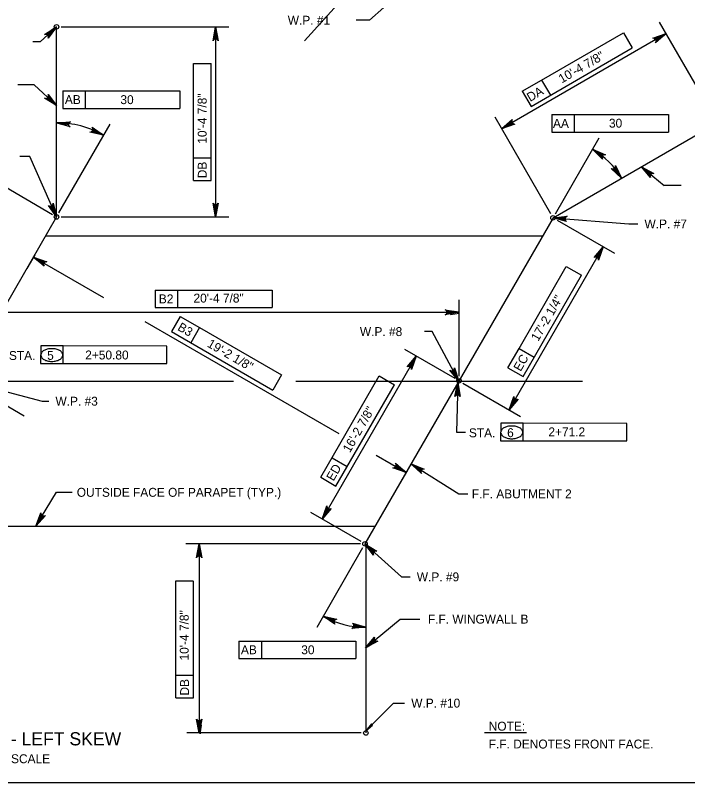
# Model space of a CAD drawing. Extents: x 179 to 454, y -271 to 54.
# Drawn here: x 226.08 to 235.14, y -87.25 to -76.92 of the extents above; entities that cross this region are included whole.
import ezdxf

# ---------------------------------------------------------------- set-up
doc = ezdxf.new("R2010")
doc.units = 0
for name, color, linetype in [('Level 1', 7, 'Continuous'), ('Level 2', 7, 'Continuous'), ('Level 3', 7, 'Continuous'), ('Level 4', 7, 'Continuous'), ('Level 41', 7, 'Continuous'), ('Level 5', 7, 'Continuous')]:
    doc.layers.add(name, color=color, linetype=linetype)

msp = doc.modelspace()

# ---------------------------------------------------------------- linework, layer by layer
at = {"layer": 'Level 1'}
msp.add_lwpolyline([(211.497, -87.25), (242.997, -87.25), (242.997, -66.75), (211.497, -66.75)], close=True, dxfattribs=at)
at = {"layer": 'Level 2'}
for p, q in [((226.635, -79.633), (226.635, -77.074)), ((233.325, -79.645), (235.541, -78.365)), ((226.635, -79.633), (224.1, -84.024)), ((233.325, -79.645), (230.79, -84.035)), ((226.488, -79.888), (233.184, -79.888)), ((225.306, -83.795), (230.928, -83.795)), ((230.803, -84.035), (230.803, -86.581)), ((232.399, -86.575), (232.968, -86.575))]:
    msp.add_line(p, q, dxfattribs=at)
at = {"layer": 'Level 3'}
for p, q in [((223.48, -81.844), (229.019, -81.844)), ((229.857, -81.844), (233.723, -81.844))]:
    msp.add_line(p, q, dxfattribs=at)
for centre in [(226.635, -77.074), (226.635, -79.633), (233.325, -79.645), (232.057, -81.84), (230.79, -84.035), (230.803, -86.581)]:
    msp.add_circle(centre, 0.0304, dxfattribs=at)
at = {"layer": 'Level 4'}
for p, q in [((235.51, -78.312), (234.76, -77.012)), ((226.696, -77.074), (228.955, -77.074)), ((228.778, -77.074), (228.778, -79.633)), ((234.848, -77.165), (232.632, -78.445)), ((233.171, -77.79), (234.273, -77.153)), ((234.273, -77.153), (234.391, -77.358)), ((233.028, -78.145), (234.391, -77.358)), ((228.48, -77.566), (228.716, -77.566)), ((228.48, -78.839), (228.48, -77.566)), ((228.716, -79.141), (228.716, -77.566)), ((232.909, -77.941), (233.171, -77.79)), ((233.171, -77.79), (233.289, -77.994)), ((226.719, -77.935), (227.022, -77.935)), ((226.719, -77.935), (226.719, -78.171)), ((227.022, -77.935), (227.022, -78.171)), ((227.022, -77.935), (228.294, -77.935)), ((228.294, -77.935), (228.294, -78.171)), ((232.909, -77.941), (233.028, -78.145)), ((226.719, -78.171), (228.294, -78.171)), ((233.294, -79.591), (232.543, -78.291)), ((233.307, -78.256), (233.609, -78.256)), ((233.307, -78.256), (233.307, -78.492)), ((233.609, -78.256), (233.609, -78.492)), ((233.609, -78.256), (234.882, -78.256)), ((234.882, -78.256), (234.882, -78.492)), ((226.666, -79.58), (227.357, -78.382)), ((233.307, -78.492), (234.882, -78.492)), ((233.356, -79.591), (233.946, -78.569)), ((228.48, -79.141), (228.48, -78.839)), ((228.48, -78.839), (228.716, -78.839)), ((226.582, -79.603), (225.859, -79.185)), ((228.48, -79.141), (228.716, -79.141)), ((234.818, -79.207), (235.049, -79.207)), ((226.696, -79.633), (228.955, -79.633)), ((233.378, -79.675), (234.154, -80.123)), ((232.733, -82.23), (234, -80.035)), ((226.34, -80.145), (226.234, -80.327)), ((226.323, -80.174), (227.266, -80.718)), ((232.866, -81.403), (233.502, -80.301)), ((233.502, -80.301), (233.707, -80.419)), ((232.92, -81.783), (233.707, -80.419)), ((227.964, -80.618), (228.266, -80.618)), ((227.964, -80.618), (227.964, -80.854)), ((228.266, -80.618), (228.266, -80.854)), ((228.266, -80.618), (229.539, -80.618)), ((229.539, -80.618), (229.539, -80.854)), ((232.058, -81.778), (232.059, -80.75)), ((227.964, -80.854), (229.539, -80.854)), ((225.369, -80.916), (232.059, -80.916)), ((228.301, -80.972), (228.183, -81.177)), ((228.301, -80.972), (228.563, -81.123)), ((227.825, -81.041), (230.44, -82.551)), ((228.183, -81.177), (229.547, -81.964)), ((228.563, -81.123), (228.445, -81.328)), ((228.563, -81.123), (229.665, -81.76)), ((226.421, -81.37), (226.42, -81.606)), ((226.723, -81.37), (226.421, -81.37)), ((228.121, -81.372), (226.723, -81.37)), ((226.723, -81.607), (226.723, -81.37)), ((228.121, -81.608), (228.121, -81.372)), ((232.715, -81.665), (232.866, -81.403)), ((232.866, -81.403), (233.071, -81.521)), ((231.481, -81.507), (230.213, -83.702)), ((232.004, -81.809), (231.327, -81.418)), ((226.42, -81.606), (228.121, -81.608)), ((232.715, -81.665), (232.92, -81.783)), ((229.665, -81.76), (229.547, -81.964)), ((230.195, -83.138), (230.983, -81.774)), ((230.983, -81.774), (231.188, -81.892)), ((225.421, -81.859), (226.2, -82.309)), ((230.4, -83.256), (231.188, -81.892)), ((232.043, -81.864), (232.023, -82.533)), ((232.111, -81.871), (232.886, -82.318)), ((232.619, -82.411), (232.618, -82.647)), ((232.921, -82.412), (232.619, -82.411)), ((234.319, -82.413), (232.921, -82.412)), ((232.921, -82.648), (232.921, -82.412)), ((234.319, -82.649), (234.319, -82.413)), ((232.023, -82.533), (232.143, -82.533)), ((232.618, -82.647), (234.319, -82.649)), ((230.941, -82.84), (231.345, -83.073)), ((230.347, -82.876), (230.551, -82.994)), ((231.412, -82.958), (232.057, -83.362)), ((231.362, -83.044), (231.256, -83.227)), ((230.195, -83.138), (230.4, -83.256)), ((226.633, -83.341), (226.847, -83.341)), ((232.057, -83.362), (232.177, -83.362)), ((230.737, -84.004), (230.06, -83.614)), ((230.728, -84.035), (228.378, -84.035)), ((228.556, -84.035), (228.556, -86.581)), ((230.759, -84.088), (230.14, -85.161)), ((228.24, -84.533), (228.47, -84.532)), ((228.24, -85.805), (228.24, -84.533)), ((228.478, -86.106), (228.478, -84.532)), ((231.265, -85.049), (231.528, -85.049)), ((229.092, -85.343), (229.394, -85.343)), ((229.092, -85.343), (229.092, -85.579)), ((229.394, -85.343), (229.394, -85.579)), ((229.394, -85.343), (230.666, -85.343)), ((230.666, -85.343), (230.666, -85.579)), ((229.092, -85.579), (230.666, -85.579)), ((228.24, -85.805), (228.476, -85.804)), ((228.242, -86.108), (228.24, -85.805)), ((228.242, -86.108), (228.478, -86.106)), ((230.741, -86.581), (228.391, -86.581))]:
    msp.add_line(p, q, dxfattribs=at)
for points in [[(231.236, -76.64), (230.851, -76.985), (230.672, -76.985)], [(226.635, -77.074), (226.415, -77.276), (226.313, -77.276)], [(234.848, -77.165), (234.704, -77.289), (234.712, -77.273), (234.712, -77.258), (234.707, -77.247), (234.699, -77.237), (234.687, -77.23), (234.669, -77.228), (234.848, -77.165), (234.687, -77.23), (234.699, -77.237), (234.848, -77.165), (234.707, -77.247), (234.712, -77.258), (234.848, -77.165), (234.712, -77.273)], [(226.635, -78.135), (226.333, -77.856)], [(232.632, -78.445), (232.776, -78.321), (232.769, -78.337), (232.768, -78.352), (232.773, -78.364), (232.781, -78.373), (232.794, -78.38), (232.811, -78.382), (232.632, -78.445), (232.794, -78.38), (232.781, -78.373), (232.632, -78.445), (232.773, -78.364), (232.768, -78.352), (232.632, -78.445), (232.769, -78.337)], [(233.857, -78.722), (234.032, -78.796), (234.014, -78.796), (234.001, -78.802), (233.993, -78.812), (233.988, -78.823), (233.987, -78.838), (233.993, -78.854), (233.857, -78.722), (233.987, -78.838), (233.988, -78.823), (233.857, -78.722), (233.993, -78.812), (234.001, -78.802), (233.857, -78.722), (234.014, -78.796)], [(226.635, -79.633), (226.275, -78.82), (226.142, -78.82)], [(234.247, -79.112), (234.11, -78.981), (234.126, -78.987), (234.141, -78.986), (234.152, -78.98), (234.161, -78.971), (234.167, -78.958), (234.166, -78.941), (234.247, -79.112), (234.167, -78.958), (234.161, -78.971), (234.247, -79.112), (234.152, -78.98), (234.141, -78.986), (234.247, -79.112), (234.126, -78.987)], [(234.515, -78.957), (234.822, -79.21)], [(234.515, -78.957), (234.681, -79.049), (234.664, -79.048), (234.65, -79.052), (234.641, -79.061), (234.634, -79.072), (234.632, -79.086), (234.637, -79.103), (234.515, -78.957), (234.632, -79.086), (234.634, -79.072), (234.515, -78.957), (234.641, -79.061), (234.65, -79.052), (234.515, -78.957), (234.664, -79.048)], [(233.325, -79.645), (233.513, -79.625), (233.498, -79.634), (233.49, -79.645), (233.487, -79.658), (233.488, -79.67), (233.494, -79.683), (233.508, -79.695), (233.325, -79.645), (233.494, -79.683), (233.488, -79.67), (233.325, -79.645), (233.487, -79.658), (233.49, -79.645), (233.325, -79.645), (233.498, -79.634)], [(233.325, -79.645), (234.345, -79.728), (234.468, -79.728)], [(234, -80.035), (233.937, -80.213), (233.936, -80.196), (233.929, -80.183), (233.919, -80.175), (233.907, -80.171), (233.892, -80.171), (233.877, -80.179), (234, -80.035), (233.892, -80.171), (233.907, -80.171), (234, -80.035), (233.919, -80.175), (233.929, -80.183), (234, -80.035), (233.936, -80.196)], [(232.059, -80.916), (231.873, -80.951), (231.887, -80.941), (231.894, -80.929), (231.896, -80.916), (231.894, -80.904), (231.887, -80.891), (231.873, -80.882), (232.059, -80.916), (231.887, -80.891), (231.894, -80.904), (232.059, -80.916), (231.896, -80.916), (231.894, -80.929), (232.059, -80.916), (231.887, -80.941)], [(232.055, -81.844), (231.696, -81.177), (231.592, -81.177)], [(231.481, -81.507), (231.418, -81.686), (231.416, -81.668), (231.409, -81.656), (231.399, -81.648), (231.388, -81.643), (231.373, -81.643), (231.357, -81.651), (231.481, -81.507), (231.373, -81.643), (231.388, -81.643), (231.481, -81.507), (231.399, -81.648), (231.409, -81.656), (231.481, -81.507), (231.416, -81.668)], [(232.055, -81.844), (231.936, -81.696), (231.951, -81.704), (231.966, -81.705), (231.978, -81.701), (231.988, -81.693), (231.995, -81.68), (231.997, -81.663), (232.055, -81.844), (231.995, -81.68), (231.988, -81.693), (232.055, -81.844), (231.978, -81.701), (231.966, -81.705), (232.055, -81.844), (231.951, -81.704)], [(225.368, -81.829), (226.44, -82.114), (226.531, -82.114)], [(232.043, -81.864), (232.072, -82.052), (232.063, -82.037), (232.051, -82.029), (232.038, -82.027), (232.026, -82.029), (232.013, -82.036), (232.003, -82.05), (232.043, -81.864), (232.013, -82.036), (232.026, -82.029), (232.043, -81.864), (232.038, -82.027), (232.051, -82.029), (232.043, -81.864), (232.063, -82.037)], [(232.733, -82.23), (232.796, -82.051), (232.797, -82.068), (232.804, -82.081), (232.814, -82.089), (232.826, -82.093), (232.84, -82.093), (232.856, -82.086), (232.733, -82.23), (232.84, -82.093), (232.826, -82.093), (232.733, -82.23), (232.814, -82.089), (232.804, -82.081), (232.733, -82.23), (232.797, -82.068)], [(231.345, -83.073), (231.166, -83.011), (231.184, -83.009), (231.196, -83.002), (231.204, -82.992), (231.209, -82.98), (231.209, -82.966), (231.201, -82.95), (231.345, -83.073), (231.209, -82.966), (231.209, -82.98), (231.345, -83.073), (231.204, -82.992), (231.196, -83.002), (231.345, -83.073), (231.184, -83.009)], [(231.412, -82.958), (231.589, -83.027), (231.571, -83.028), (231.558, -83.034), (231.55, -83.044), (231.545, -83.056), (231.545, -83.07), (231.552, -83.086), (231.412, -82.958), (231.545, -83.07), (231.545, -83.056), (231.412, -82.958), (231.55, -83.044), (231.558, -83.034), (231.412, -82.958), (231.571, -83.028)], [(226.357, -83.795), (226.633, -83.341)], [(230.213, -83.702), (230.276, -83.523), (230.278, -83.541), (230.285, -83.553), (230.295, -83.561), (230.306, -83.566), (230.321, -83.566), (230.337, -83.558), (230.213, -83.702), (230.321, -83.566), (230.306, -83.566), (230.213, -83.702), (230.295, -83.561), (230.285, -83.553), (230.213, -83.702), (230.278, -83.541)], [(226.357, -83.795), (226.424, -83.618), (226.425, -83.635), (226.432, -83.648), (226.441, -83.656), (226.453, -83.661), (226.468, -83.661), (226.484, -83.654), (226.357, -83.795), (226.468, -83.661), (226.453, -83.661), (226.357, -83.795), (226.441, -83.656), (226.432, -83.648), (226.357, -83.795), (226.425, -83.635)], [(228.556, -84.035), (228.591, -84.222), (228.581, -84.207), (228.568, -84.2), (228.556, -84.198), (228.543, -84.2), (228.531, -84.207), (228.521, -84.222), (228.556, -84.035), (228.531, -84.207), (228.543, -84.2), (228.556, -84.035), (228.556, -84.198), (228.568, -84.2), (228.556, -84.035), (228.581, -84.207)], [(230.79, -84.035), (231.284, -84.479), (231.401, -84.479)], [(230.79, -84.035), (230.952, -84.134), (230.935, -84.131), (230.921, -84.136), (230.911, -84.144), (230.904, -84.154), (230.901, -84.169), (230.905, -84.186), (230.79, -84.035), (230.901, -84.169), (230.904, -84.154), (230.79, -84.035), (230.911, -84.144), (230.921, -84.136), (230.79, -84.035), (230.935, -84.131)], [(230.228, -85.008), (230.413, -85.051), (230.396, -85.054), (230.384, -85.062), (230.377, -85.073), (230.374, -85.085), (230.376, -85.1), (230.385, -85.115), (230.228, -85.008), (230.376, -85.1), (230.374, -85.085), (230.228, -85.008), (230.377, -85.073), (230.384, -85.062), (230.228, -85.008), (230.396, -85.054)], [(230.803, -85.157), (230.613, -85.173), (230.629, -85.164), (230.637, -85.153), (230.641, -85.14), (230.64, -85.128), (230.634, -85.114), (230.621, -85.103), (230.803, -85.157), (230.634, -85.114), (230.64, -85.128), (230.803, -85.157), (230.641, -85.14), (230.637, -85.153), (230.803, -85.157), (230.629, -85.164)], [(230.797, -85.434), (231.265, -85.049)], [(230.797, -85.434), (230.919, -85.289), (230.914, -85.305), (230.916, -85.32), (230.922, -85.331), (230.932, -85.339), (230.946, -85.344), (230.963, -85.343), (230.797, -85.434), (230.946, -85.344), (230.932, -85.339), (230.797, -85.434), (230.922, -85.331), (230.916, -85.32), (230.797, -85.434), (230.914, -85.305)], [(230.803, -86.551), (231.174, -86.179), (231.325, -86.179)], [(228.556, -86.581), (228.521, -86.395), (228.531, -86.409), (228.543, -86.417), (228.556, -86.419), (228.568, -86.417), (228.581, -86.409), (228.591, -86.395), (228.556, -86.581), (228.581, -86.409), (228.568, -86.417), (228.556, -86.581), (228.556, -86.419), (228.543, -86.417), (228.556, -86.581), (228.531, -86.409)]]:
    msp.add_lwpolyline(points, dxfattribs=at)
for points in [[(226.635, -77.074), (226.541, -77.147), (226.555, -77.161)], [(228.758, -77.192), (228.797, -77.192), (228.778, -77.074)], [(234.736, -77.207), (234.756, -77.241), (234.848, -77.165)], [(226.635, -78.135), (226.555, -78.048), (226.542, -78.062)], [(232.725, -78.369), (232.744, -78.403), (232.632, -78.445)], [(226.635, -79.633), (226.596, -79.522), (226.578, -79.529)], [(228.758, -79.515), (228.797, -79.515), (228.778, -79.633)], [(233.325, -79.645), (233.442, -79.664), (233.443, -79.644)], [(233.924, -80.127), (233.958, -80.147), (234, -80.035)], [(226.435, -80.216), (226.415, -80.25), (226.323, -80.174)], [(231.941, -80.908), (231.941, -80.947), (232.059, -80.927)], [(231.405, -81.599), (231.439, -81.619), (231.481, -81.507)], [(232.055, -81.844), (232.008, -81.735), (231.99, -81.745)], [(232.019, -81.985), (232.059, -81.986), (232.044, -81.866)], [(232.775, -82.118), (232.809, -82.137), (232.733, -82.23)], [(231.253, -82.997), (231.233, -83.031), (231.345, -83.073)], [(231.519, -83.048), (231.54, -83.014), (231.428, -82.968)], [(230.255, -83.59), (230.289, -83.61), (230.213, -83.702)], [(226.357, -83.795), (226.427, -83.699), (226.41, -83.689)], [(228.575, -84.164), (228.536, -84.164), (228.555, -84.046)], [(230.79, -84.035), (230.871, -84.121), (230.884, -84.107)], [(230.797, -85.434), (230.894, -85.367), (230.882, -85.352)], [(230.803, -86.551), (230.893, -86.474), (230.879, -86.46)], [(228.587, -86.474), (228.548, -86.474), (228.568, -86.592)]]:
    msp.add_lwpolyline(points, close=True, dxfattribs=at)
for centre, radius, start, end in [((226.635, -79.633), 1.268, 60.0012, 89.9999), ((233.325, -79.645), 1.065, 30, 60.0009), ((226.57, -81.667), 0.26, 90, 103.3749), ((226.57, -81.667), 0.26, 76.6251, 90), ((226.472, -81.492), 0.0513, 144.1862, 180), ((226.472, -81.492), 0.0513, 180, 215.8138), ((226.519, -81.526), 0.109, 119.8571, 144.1862), ((226.55, -81.581), 0.172, 103.3749, 119.8571), ((226.591, -81.581), 0.172, 60.1429, 76.6251), ((226.622, -81.526), 0.109, 35.8138, 60.1429), ((226.669, -81.492), 0.0513, 0, 35.8138), ((226.669, -81.492), 0.0513, 324.1862, 0), ((226.519, -81.458), 0.109, 215.8138, 240.1429), ((226.55, -81.404), 0.172, 240.1429, 256.6251), ((226.57, -81.318), 0.26, 256.6251, 270), ((226.57, -81.318), 0.26, 270, 283.3749), ((226.591, -81.404), 0.172, 283.3749, 299.8571), ((226.622, -81.458), 0.109, 299.8571, 324.1862), ((232.67, -82.534), 0.0513, 144.1862, 180), ((232.67, -82.534), 0.0513, 180, 215.8138), ((232.717, -82.567), 0.109, 119.8571, 144.1862), ((232.748, -82.622), 0.172, 103.3749, 119.8571), ((232.768, -82.708), 0.26, 90, 103.3749), ((232.768, -82.708), 0.26, 76.6251, 90), ((232.789, -82.622), 0.172, 60.1429, 76.6251), ((232.82, -82.567), 0.109, 35.8138, 60.1429), ((232.867, -82.534), 0.0513, 0, 35.8138), ((232.867, -82.534), 0.0513, 324.1862, 0), ((232.717, -82.5), 0.109, 215.8138, 240.1429), ((232.748, -82.445), 0.172, 240.1429, 256.6251), ((232.768, -82.359), 0.26, 256.6251, 270), ((232.768, -82.359), 0.26, 270, 283.3749), ((232.789, -82.445), 0.172, 283.3749, 299.8571), ((232.82, -82.5), 0.109, 299.8571, 324.1862), ((230.79, -84.035), 1.123, 240.0012, 270.656)]:
    msp.add_arc(centre, radius, start, end, dxfattribs=at)
at = {"layer": 'Level 41'}
msp.add_line((239.183, -67.11), (229.977, -77.261), dxfattribs=at)
at = {"layer": 'Level 5'}
msp.add_line((226.333, -77.856), (226.112, -77.856), dxfattribs=at)
for points in [[(226.635, -77.074), (226.521, -77.226), (226.525, -77.209), (226.522, -77.195), (226.515, -77.184), (226.505, -77.176), (226.491, -77.172), (226.474, -77.175), (226.635, -77.074), (226.491, -77.172), (226.505, -77.176), (226.635, -77.074), (226.515, -77.184), (226.522, -77.195), (226.635, -77.074), (226.525, -77.209)], [(228.778, -77.074), (228.812, -77.261), (228.802, -77.246), (228.79, -77.239), (228.778, -77.237), (228.765, -77.239), (228.752, -77.246), (228.743, -77.261), (228.778, -77.074), (228.752, -77.246), (228.765, -77.239), (228.778, -77.074), (228.778, -77.237), (228.79, -77.239), (228.778, -77.074), (228.802, -77.246)], [(226.635, -78.135), (226.474, -78.034), (226.492, -78.037), (226.506, -78.033), (226.516, -78.025), (226.523, -78.014), (226.526, -78), (226.522, -77.983), (226.635, -78.135), (226.526, -78), (226.523, -78.014), (226.635, -78.135), (226.516, -78.025), (226.506, -78.033), (226.635, -78.135), (226.492, -78.037)], [(226.635, -78.365), (226.824, -78.351), (226.809, -78.359), (226.8, -78.37), (226.797, -78.383), (226.797, -78.395), (226.803, -78.409), (226.817, -78.42), (226.635, -78.365), (226.803, -78.409), (226.797, -78.395), (226.635, -78.365), (226.797, -78.383), (226.8, -78.37), (226.635, -78.365), (226.809, -78.359)], [(227.269, -78.534), (227.085, -78.49), (227.102, -78.486), (227.114, -78.478), (227.121, -78.468), (227.124, -78.455), (227.122, -78.441), (227.113, -78.426), (227.269, -78.534), (227.122, -78.441), (227.124, -78.455), (227.269, -78.534), (227.121, -78.468), (227.114, -78.478), (227.269, -78.534), (227.102, -78.486)], [(226.635, -79.633), (226.528, -79.477), (226.542, -79.486), (226.557, -79.488), (226.569, -79.485), (226.58, -79.478), (226.588, -79.466), (226.591, -79.449), (226.635, -79.633), (226.588, -79.466), (226.58, -79.478), (226.635, -79.633), (226.569, -79.485), (226.557, -79.488), (226.635, -79.633), (226.542, -79.486)], [(228.778, -79.633), (228.743, -79.447), (228.752, -79.461), (228.765, -79.469), (228.778, -79.471), (228.79, -79.469), (228.802, -79.461), (228.812, -79.447), (228.778, -79.633), (228.802, -79.461), (228.79, -79.469), (228.778, -79.633), (228.778, -79.471), (228.765, -79.469), (228.778, -79.633), (228.752, -79.461)], [(226.323, -80.174), (226.502, -80.237), (226.484, -80.238), (226.472, -80.245), (226.464, -80.255), (226.459, -80.267), (226.459, -80.282), (226.467, -80.297), (226.323, -80.174), (226.459, -80.282), (226.459, -80.267), (226.323, -80.174), (226.464, -80.255), (226.472, -80.245), (226.323, -80.174), (226.484, -80.238)]]:
    msp.add_lwpolyline(points, dxfattribs=at)

# ---------------------------------------------------------------- texts
at = {"layer": 'Level 2'}
for s, p in [('NOTE:', (232.458, -86.55)), ('F.F. DENOTES FRONT FACE.', (232.458, -86.79))]:
    msp.add_text(s, height=0.12, dxfattribs=at).set_placement(p)
at = {"layer": 'Level 4'}
for s, height, p in [('W.P. #1', 0.12, (229.75, -77.045)), ('AB', 0.12, (226.747, -78.113)), ('AA', 0.12, (233.324, -78.434)), ('W.P. #7', 0.12, (234.557, -79.788)), ('B2', 0.12, (228.013, -80.796)), ('W.P. #8', 0.12, (230.722, -81.237)), ('STA.', 0.12, (225.993, -81.559)), ('W.P. #3', 0.12, (226.62, -82.174)), ('STA.', 0.12, (232.191, -82.6)), ('OUTSIDE FACE OF PARAPET (TYP.)', 0.12, (226.907, -83.401)), ('F.F. ABUTMENT 2', 0.12, (232.23, -83.422)), ('W.P. #9', 0.12, (231.489, -84.539)), ('F.F. WINGWALL B', 0.12, (231.638, -85.108)), ('AB', 0.12, (229.119, -85.521)), ('W.P. #10', 0.12, (231.414, -86.239)), ('STAKE-OUT PLAN - LEFT SKEW', 0.17717, (223.912, -86.748)), ('NO SCALE', 0.12, (225.736, -86.988))]:
    msp.add_text(s, height=height, dxfattribs=at).set_placement(p)
for s, rotation, p in [('DA', 30, (233.015, -78.086)), ('DB', 90, (228.658, -79.112)), ('B3', 330, (228.255, -81.151)), ('5', 359.9382, (226.508, -81.557)), ('EC', 60, (232.888, -81.722)), ('6', 359.9382, (232.706, -82.598)), ('ED', 60, (230.366, -83.198)), ('DB', 90.2891, (228.42, -86.077))]:
    msp.add_text(s, height=0.12, rotation=rotation, dxfattribs=at).set_placement(p)
at = {"layer": 'Level 41'}
for s, rotation, p in [('10\'-4 7/8"', 29.9983, (233.442, -77.837)), ('10\'-4 7/8"', 90, (228.657, -78.647)), ('17\'-2 1/4"', 60.0002, (233.124, -81.317)), ('19\'-2 1/8"', 329.9995, (228.654, -81.374)), ('16\'-2 7/8"', 60.0002, (230.587, -82.816)), ('10\'-4 7/8"', 90, (228.415, -85.605))]:
    msp.add_text(s, height=0.12, rotation=rotation, dxfattribs=at).set_placement(p)
for s, p in [('30', (227.495, -78.114)), ('30', (234.078, -78.431)), ('20\'-4 7/8"', (228.48, -80.786)), ('2+50.80', (227.021, -81.552)), ('2+71.2', (233.262, -82.587)), ('30', (229.932, -85.521))]:
    msp.add_text(s, height=0.12, dxfattribs=at).set_placement(p)

doc.saveas('drawing.dxf')
